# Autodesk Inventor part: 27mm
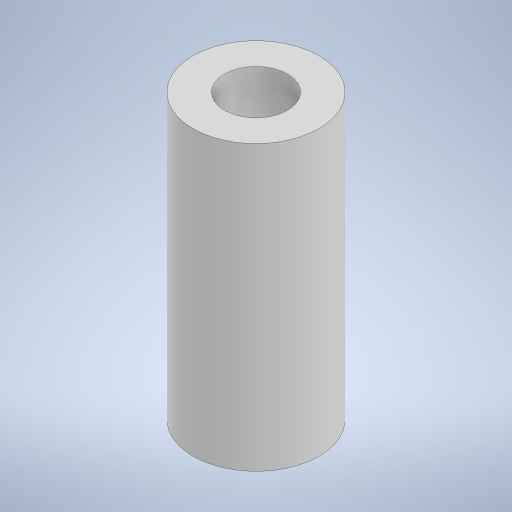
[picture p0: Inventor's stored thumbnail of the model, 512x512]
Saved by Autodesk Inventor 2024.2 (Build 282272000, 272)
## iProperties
Created: 2024-05
Part Number: 27mm
Material: Generic
Document SubType Name: Modeling
Designer: Karsten
Density: 1 g/cm^3
Appearance: Default
Author: Karsten
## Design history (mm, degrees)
sketch "Sketch1"
  geometry: C1 r 3 at (0, 0); C2 r 6 at (0, 0); 1 further point
  constraints: 2 centre point, 2 coincident
  dimensions: "d0" = 6 diameter of C1; "d1" = 12 diameter of C2
extrude "Extrusion1" new body sketch "Sketch1" distance "d2" = 27; taper "d3" = 0 deg
body "Solid1"
